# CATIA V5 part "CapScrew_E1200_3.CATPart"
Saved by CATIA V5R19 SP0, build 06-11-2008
Part number: CapScrew_E1200_3
Nomenclature: E 1200/6x30
Source: Unknown
Description: MEUSBURGER
Bounding box of the stored display mesh (mm): x -4.991 to 4.998, y -5 to 5, z 0 to 36
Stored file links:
  C:\Users\jsmid\Desktop\DP_Smidak_Forma LEGO\CapScrew_E1200_3.CATPart
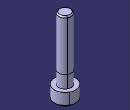
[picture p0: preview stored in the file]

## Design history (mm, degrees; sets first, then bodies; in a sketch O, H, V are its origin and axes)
Body1 (main body)
  Solid1 "PartBody": solid without history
